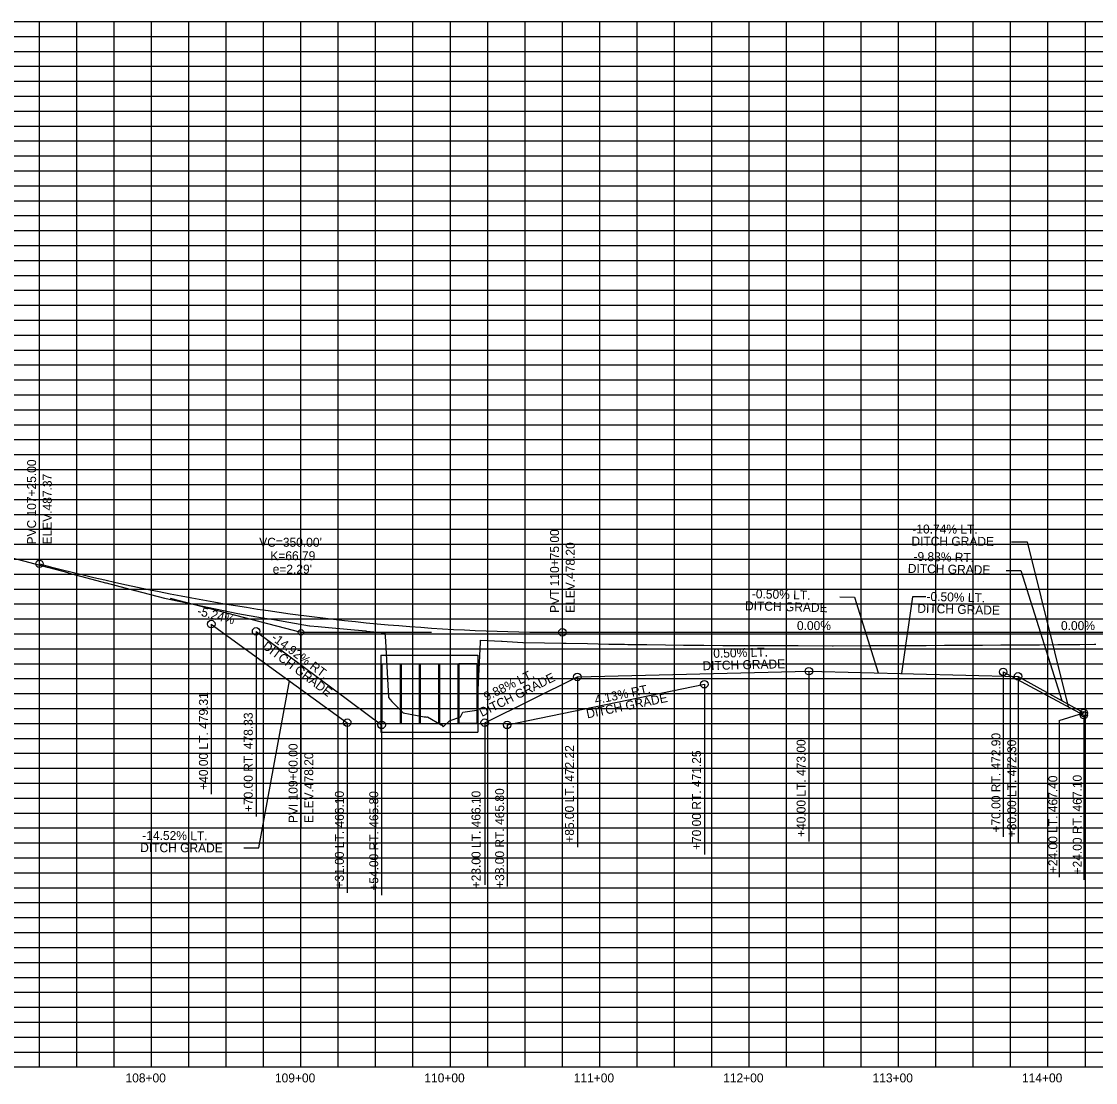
# Model space of a CAD drawing. Extents: x 1054002 to 1056762, y 395173 to 397393.
# Drawn here: x 1054745 to 1055464, y 396673 to 397383 of the extents above; entities that cross this region are included whole.
import ezdxf

# ---------------------------------------------------------------- set-up
doc = ezdxf.new("R2010")
doc.units = 0
for name, color, linetype in [('R_Axis_Annotation', 7, 'Continuous'), ('R_Drainage', 7, 'Continuous'), ('R_Exist Surface', 7, 'Continuous'), ('R_Grid', 7, 'Continuous'), ('R_Grid_Minor', 7, 'Continuous'), ('R_Vert Alg', 7, 'Continuous'), ('R_Vert Alg Annot', 7, 'Continuous')]:
    doc.layers.add(name, color=color, linetype=linetype)

msp = doc.modelspace()

# ---------------------------------------------------------------- linework, layer by layer
at = {"layer": 'R_Drainage'}
for p, q in [((1054985.8, 396959.15), (1054985.8, 396907.48)), ((1054985.8, 396959.15), (1055050.79, 396959.15)), ((1055050.79, 396959.15), (1055050.79, 396907.48)), ((1054986.48, 396953.31), (1054986.48, 396913.31)), ((1054986.48, 396953.31), (1054998.66, 396953.31)), ((1054998.66, 396953.31), (1054998.66, 396913.31)), ((1054999.34, 396953.31), (1054999.34, 396913.31)), ((1054999.34, 396953.31), (1055011.52, 396953.31)), ((1055011.52, 396953.31), (1055011.52, 396913.31)), ((1055012.2, 396953.31), (1055012.2, 396913.31)), ((1055012.2, 396953.31), (1055024.38, 396953.31)), ((1055024.38, 396953.31), (1055024.38, 396913.31)), ((1055025.06, 396953.31), (1055025.06, 396913.31)), ((1055025.06, 396953.31), (1055037.25, 396953.31)), ((1055037.25, 396953.31), (1055037.25, 396913.31)), ((1055037.92, 396953.31), (1055037.92, 396913.31)), ((1055050.11, 396953.31), (1055037.92, 396953.31)), ((1055050.11, 396953.31), (1055050.11, 396913.31)), ((1054986.48, 396913.31), (1054998.66, 396913.31)), ((1054999.34, 396913.31), (1055011.52, 396913.31)), ((1055012.2, 396913.31), (1055024.38, 396913.31)), ((1055025.06, 396913.31), (1055037.25, 396913.31)), ((1055050.11, 396913.31), (1055037.92, 396913.31)), ((1054985.8, 396907.48), (1055050.79, 396907.48))]:
    msp.add_line(p, q, dxfattribs=at)
at = {"layer": 'R_Exist Surface'}
msp.add_lwpolyline([(1054738.07, 397024.45), (1054750.91, 397021.1), (1054750.96, 397021.09), (1054762.42, 397018.05), (1054763.61, 397017.73), (1054776.24, 397014.37), (1054776.36, 397014.34), (1054788.99, 397010.97), (1054801.5, 397007.64), (1054801.84, 397007.55), (1054821.23, 397002.51), (1054821.42, 397002.45), (1054840.9, 396997.39), (1054840.92, 396997.38), (1054865.44, 396992.17), (1054865.46, 396992.17), (1054865.48, 396992.16), (1054890.01, 396986.95), (1054890.03, 396986.95), (1054890.06, 396986.94), (1054906.49, 396984.18), (1054914.1, 396982.89), (1054914.12, 396982.89), (1054938.12, 396978.85), (1054938.2, 396978.83), (1054943.83, 396978.31), (1054950.71, 396977.67), (1054950.83, 396977.65), (1054963.34, 396976.48), (1054975.63, 396975.32), (1054976.18, 396975.25), (1054988.47, 396974.09), (1054988.8, 396968.47), (1054991.01, 396930.7), (1054993.2, 396928.06), (1055000.64, 396920.56), (1055014.75, 396917.87), (1055015.95, 396917.83), (1055016.53, 396917.71), (1055016.93, 396917.93), (1055026.19, 396912.4), (1055026.58, 396912.41), (1055027.38, 396911.12), (1055031.82, 396915.26), (1055039.18, 396917.73), (1055040.63, 396920.89), (1055050.03, 396922.22), (1055050.17, 396922.27), (1055052.49, 396967.72), (1055052.55, 396969.21), (1055066.53, 396968.46), (1055066.9, 396968.44), (1055077.14, 396967.89), (1055080.92, 396967.67), (1055081.05, 396967.67), (1055095.37, 396967.39), (1055107.85, 396967.15), (1055109.76, 396967.12), (1055109.77, 396967.12), (1055124.16, 396966.84), (1055138.46, 396966.56), (1055138.62, 396966.56), (1055148.83, 396966.4), (1055151.12, 396966.37), (1055163.56, 396966.17), (1055163.77, 396966.16), (1055176.2, 396965.96), (1055188.44, 396965.76), (1055189, 396965.75), (1055201.86, 396965.71), (1055214.68, 396965.66), (1055215.3, 396965.67), (1055228.12, 396965.62), (1055228.77, 396965.63), (1055241.59, 396965.58), (1055264.46, 396965.5), (1055265.11, 396965.5), (1055288.02, 396965.43), (1055288.62, 396965.43), (1055313.1, 396965.53), (1055313.33, 396965.53), (1055327.32, 396965.59), (1055338, 396965.63), (1055338.1, 396965.63), (1055350.53, 396965.69), (1055350.67, 396965.69), (1055363.05, 396965.75), (1055363.25, 396965.75), (1055375.58, 396965.81), (1055375.82, 396965.8), (1055388.1, 396965.86), (1055388.4, 396965.86), (1055400.72, 396965.93), (1055401.36, 396965.94), (1055413.68, 396966.02), (1055425.92, 396966.09), (1055426.71, 396966.1), (1055438.95, 396966.18), (1055452.82, 396966.29), (1055453.62, 396966.3), (1055463.37, 396966.38), (1055464.37, 396966.39)], dxfattribs=at)
at = {"layer": 'R_Grid'}
for p, q in [((1054032.29, 397383.41), (1056732.29, 397383.41)), ((1054032.29, 397383.41), (1056732.29, 397383.41)), ((1054832.29, 396683.41), (1054832.29, 397383.41)), ((1054932.29, 396683.41), (1054932.29, 397383.41)), ((1055032.29, 396683.41), (1055032.29, 397383.41)), ((1055132.29, 396683.41), (1055132.29, 397383.41)), ((1055232.29, 396683.41), (1055232.29, 397383.41)), ((1055332.29, 396683.41), (1055332.29, 397383.41)), ((1055432.29, 396683.41), (1055432.29, 397383.41)), ((1054032.29, 397333.41), (1056732.29, 397333.41)), ((1054032.29, 397283.41), (1056732.29, 397283.41)), ((1054032.29, 397233.41), (1056732.29, 397233.41)), ((1054032.29, 397183.41), (1056732.29, 397183.41)), ((1054032.29, 397133.41), (1056732.29, 397133.41)), ((1054032.29, 397083.41), (1056732.29, 397083.41)), ((1054032.29, 397033.41), (1056732.29, 397033.41)), ((1054032.29, 396983.41), (1056732.29, 396983.41)), ((1054032.29, 396933.41), (1056732.29, 396933.41)), ((1054032.29, 396883.41), (1056732.29, 396883.41)), ((1054032.29, 396833.41), (1056732.29, 396833.41)), ((1054032.29, 396783.41), (1056732.29, 396783.41)), ((1054032.29, 396733.41), (1056732.29, 396733.41)), ((1054032.29, 396683.41), (1056732.29, 396683.41))]:
    msp.add_line(p, q, dxfattribs=at)
at = {"layer": 'R_Grid_Minor'}
for p, q in [((1054757.29, 396683.41), (1054757.29, 397383.41)), ((1054782.29, 396683.41), (1054782.29, 397383.41)), ((1054807.29, 396683.41), (1054807.29, 397383.41)), ((1054857.29, 396683.41), (1054857.29, 397383.41)), ((1054882.29, 396683.41), (1054882.29, 397383.41)), ((1054907.29, 396683.41), (1054907.29, 397383.41)), ((1054957.29, 396683.41), (1054957.29, 397383.41)), ((1054982.29, 396683.41), (1054982.29, 397383.41)), ((1055007.29, 396683.41), (1055007.29, 397383.41)), ((1055057.29, 396683.41), (1055057.29, 397383.41)), ((1055082.29, 396683.41), (1055082.29, 397383.41)), ((1055107.29, 396683.41), (1055107.29, 397383.41)), ((1055157.29, 396683.41), (1055157.29, 397383.41)), ((1055182.29, 396683.41), (1055182.29, 397383.41)), ((1055207.29, 396683.41), (1055207.29, 397383.41)), ((1055257.29, 396683.41), (1055257.29, 397383.41)), ((1055282.29, 396683.41), (1055282.29, 397383.41)), ((1055307.29, 396683.41), (1055307.29, 397383.41)), ((1055357.29, 396683.41), (1055357.29, 397383.41)), ((1055382.29, 396683.41), (1055382.29, 397383.41)), ((1055407.29, 396683.41), (1055407.29, 397383.41)), ((1055457.29, 396683.41), (1055457.29, 397383.41)), ((1054032.29, 397373.41), (1056732.29, 397373.41)), ((1054032.29, 397363.41), (1056732.29, 397363.41)), ((1054032.29, 397353.41), (1056732.29, 397353.41)), ((1054032.29, 397343.41), (1056732.29, 397343.41)), ((1054032.29, 397323.41), (1056732.29, 397323.41)), ((1054032.29, 397313.41), (1056732.29, 397313.41)), ((1054032.29, 397303.41), (1056732.29, 397303.41)), ((1054032.29, 397293.41), (1056732.29, 397293.41)), ((1054032.29, 397273.41), (1056732.29, 397273.41)), ((1054032.29, 397263.41), (1056732.29, 397263.41)), ((1054032.29, 397253.41), (1056732.29, 397253.41)), ((1054032.29, 397243.41), (1056732.29, 397243.41)), ((1054032.29, 397223.41), (1056732.29, 397223.41)), ((1054032.29, 397213.41), (1056732.29, 397213.41)), ((1054032.29, 397203.41), (1056732.29, 397203.41)), ((1054032.29, 397193.41), (1056732.29, 397193.41)), ((1054032.29, 397173.41), (1056732.29, 397173.41)), ((1054032.29, 397163.41), (1056732.29, 397163.41)), ((1054032.29, 397153.41), (1056732.29, 397153.41)), ((1054032.29, 397143.41), (1056732.29, 397143.41)), ((1054032.29, 397123.41), (1056732.29, 397123.41)), ((1054032.29, 397113.41), (1056732.29, 397113.41)), ((1054032.29, 397103.41), (1056732.29, 397103.41)), ((1054032.29, 397093.41), (1056732.29, 397093.41)), ((1054032.29, 397073.41), (1056732.29, 397073.41)), ((1054032.29, 397063.41), (1056732.29, 397063.41)), ((1054032.29, 397053.41), (1056732.29, 397053.41)), ((1054032.29, 397043.41), (1056732.29, 397043.41)), ((1054032.29, 397023.41), (1056732.29, 397023.41)), ((1054032.29, 397013.41), (1056732.29, 397013.41)), ((1054032.29, 397003.41), (1056732.29, 397003.41)), ((1054032.29, 396993.41), (1056732.29, 396993.41)), ((1054032.29, 396973.41), (1056732.29, 396973.41)), ((1054032.29, 396963.41), (1056732.29, 396963.41)), ((1054032.29, 396953.41), (1056732.29, 396953.41)), ((1054032.29, 396943.41), (1056732.29, 396943.41)), ((1054032.29, 396923.41), (1056732.29, 396923.41)), ((1054032.29, 396913.41), (1056732.29, 396913.41)), ((1054032.29, 396903.41), (1056732.29, 396903.41)), ((1054032.29, 396893.41), (1056732.29, 396893.41)), ((1054032.29, 396873.41), (1056732.29, 396873.41)), ((1054032.29, 396863.41), (1056732.29, 396863.41)), ((1054032.29, 396853.41), (1056732.29, 396853.41)), ((1054032.29, 396843.41), (1056732.29, 396843.41)), ((1054032.29, 396823.41), (1056732.29, 396823.41)), ((1054032.29, 396813.41), (1056732.29, 396813.41)), ((1054032.29, 396803.41), (1056732.29, 396803.41)), ((1054032.29, 396793.41), (1056732.29, 396793.41)), ((1054032.29, 396773.41), (1056732.29, 396773.41)), ((1054032.29, 396763.41), (1056732.29, 396763.41)), ((1054032.29, 396753.41), (1056732.29, 396753.41)), ((1054032.29, 396743.41), (1056732.29, 396743.41)), ((1054032.29, 396723.41), (1056732.29, 396723.41)), ((1054032.29, 396713.41), (1056732.29, 396713.41)), ((1054032.29, 396703.41), (1056732.29, 396703.41)), ((1054032.29, 396693.41), (1056732.29, 396693.41))]:
    msp.add_line(p, q, dxfattribs=at)
at = {"layer": 'R_Vert Alg'}
for p, q in [((1054872.29, 396979.96), (1054963.29, 396913.91)), ((1054902.29, 396975.06), (1054986.29, 396912.41)), ((1055107.29, 396974.41), (1055802.29, 396974.41)), ((1055117.29, 396944.54), (1055272.29, 396948.41)), ((1055272.29, 396948.41), (1055412.29, 396944.91)), ((1055402.29, 396947.91), (1055456.29, 396918.92)), ((1055412.29, 396944.91), (1055456.27, 396920.43)), ((1055055.29, 396913.91), (1055117.29, 396944.54)), ((1055070.29, 396912.41), (1055202.29, 396939.66))]:
    msp.add_line(p, q, dxfattribs=at)
msp.add_lwpolyline([(1054757.29, 397020.26), (1054764.58, 397018.37), (1054771.88, 397016.52), (1054779.17, 397014.71), (1054786.46, 397012.94), (1054793.75, 397011.21), (1054801.04, 397009.52), (1054808.33, 397007.87), (1054815.63, 397006.25), (1054822.92, 397004.68), (1054830.21, 397003.15), (1054837.5, 397001.66), (1054844.79, 397000.2), (1054852.08, 396998.79), (1054859.38, 396997.42), (1054866.67, 396996.08), (1054873.96, 396994.79), (1054881.25, 396993.54), (1054888.54, 396992.32), (1054895.83, 396991.15), (1054903.13, 396990.01), (1054910.42, 396988.92), (1054917.71, 396987.87), (1054925, 396986.85), (1054939.58, 396984.94), (1054946.88, 396984.04), (1054954.17, 396983.19), (1054961.46, 396982.37), (1054968.75, 396981.6), (1054976.04, 396980.86), (1054983.33, 396980.16), (1054990.63, 396979.51), (1054997.92, 396978.89), (1055005.21, 396978.31), (1055012.5, 396977.78), (1055019.79, 396977.28), (1055027.08, 396976.82), (1055034.38, 396976.4), (1055041.67, 396976.02), (1055048.96, 396975.69), (1055056.25, 396975.39), (1055063.54, 396975.13), (1055070.83, 396974.91), (1055078.13, 396974.73), (1055085.42, 396974.59), (1055092.71, 396974.49), (1055100, 396974.43), (1055107.29, 396974.41)], dxfattribs=at)
at = {"layer": 'R_Vert Alg Annot'}
for p, q in [((1054757.29, 397030.26), (1054757.29, 397114.26)), ((1055107.29, 396984.41), (1055107.29, 397068.41)), ((1054757.29, 397020.26), (1054757.29, 397030.26)), ((1054844.79, 396997.34), (1054932.29, 396974.41)), ((1055107.29, 396974.41), (1055107.29, 396984.41)), ((1054872.29, 396979.96), (1054872.29, 396949.96)), ((1054902.29, 396975.06), (1054902.29, 396935.06)), ((1054932.29, 396974.41), (1055019.79, 396974.41)), ((1054932.29, 396974.41), (1054932.29, 396927.7)), ((1054872.29, 396949.96), (1054872.29, 396865.96)), ((1055272.29, 396948.41), (1055272.29, 396918.41)), ((1055402.29, 396947.91), (1055402.29, 396921.53)), ((1055412.29, 396944.91), (1055412.29, 396917.52)), ((1055117.29, 396944.54), (1055117.29, 396914.54)), ((1055202.29, 396939.66), (1055202.29, 396909.66)), ((1054902.29, 396935.06), (1054902.29, 396851.06)), ((1054932.29, 396927.7), (1054932.29, 396843.7)), ((1055272.29, 396918.41), (1055272.29, 396834.41)), ((1055402.29, 396921.53), (1055402.29, 396837.53)), ((1055412.29, 396917.52), (1055412.29, 396833.52)), ((1055439.82, 396915.47), (1055456.27, 396920.43)), ((1055456.29, 396918.92), (1055456.29, 396808.73)), ((1054963.29, 396913.91), (1054963.29, 396883.91)), ((1054986.29, 396912.41), (1054986.29, 396882.41)), ((1055055.29, 396913.91), (1055055.29, 396882.53)), ((1055070.29, 396912.41), (1055070.29, 396881.46)), ((1055117.29, 396914.54), (1055117.29, 396830.54)), ((1055202.29, 396909.66), (1055202.29, 396825.66)), ((1055439.82, 396915.47), (1055439.82, 396810.4)), ((1054963.29, 396883.91), (1054963.29, 396799.91)), ((1054986.29, 396882.41), (1054986.29, 396798.41)), ((1055055.29, 396882.53), (1055055.29, 396805.29)), ((1055070.29, 396881.46), (1055070.29, 396804.22))]:
    msp.add_line(p, q, dxfattribs=at)
for points in [[(1055407.82, 397035.08), (1055418.46, 397035.05), (1055445.74, 396924.58)], [(1055404.38, 397015.78), (1055414.18, 397015.74), (1055441.46, 396928.66)], [(1055293.01, 396998.08), (1055302.82, 396998.04), (1055318.73, 396947.25)], [(1055350.57, 396998.13), (1055341.56, 396998.09), (1055334.22, 396946.86)], [(1054894.03, 396830.17), (1054904.21, 396830.23), (1054924.61, 396941.99)]]:
    msp.add_lwpolyline(points, dxfattribs=at)
for centre, radius in [((1054757.29, 397020.26), 2.5), ((1054872.29, 396979.96), 2.5), ((1054902.29, 396975.06), 2.5), ((1054932.29, 396974.41), 1.85), ((1055107.29, 396974.41), 2.5), ((1055117.29, 396944.54), 2.5), ((1055272.29, 396948.41), 2.5), ((1055402.29, 396947.91), 2.5), ((1055412.29, 396944.91), 2.5), ((1055202.29, 396939.66), 2.5), ((1054963.29, 396913.91), 2.5), ((1055055.29, 396913.91), 2.5), ((1055456.27, 396920.43), 2.5), ((1055456.29, 396918.92), 2.5), ((1054986.29, 396912.41), 2.5), ((1055070.29, 396912.41), 2.5)]:
    msp.add_circle(centre, radius, dxfattribs=at)

# ---------------------------------------------------------------- texts
at = {"layer": 'R_Axis_Annotation'}
for s, p in [('108+00', (1054814.89, 396673.06)), ('109+00', (1054914.89, 396673.06)), ('110+00', (1055014.89, 396673.06)), ('111+00', (1055114.89, 396673.06)), ('112+00', (1055214.89, 396673.06)), ('113+00', (1055314.89, 396673.06)), ('114+00', (1055414.89, 396673.06))]:
    msp.add_text(s, height=6, dxfattribs=at).set_placement(p)
at = {"layer": 'R_Vert Alg Annot'}
for s, rotation, p in [('PVC 107+25.00', 90, (1054755.04, 397033.26)), ('ELEV.487.37', 90, (1054765.54, 397033.26)), (' -10.74% LT.', 359.82298, (1055339.28, 397040.62)), ('PVT 110+75.00', 90, (1055105.04, 396987.41)), ('DITCH GRADE', 359.82298, (1055340.88, 397032.49)), ('ELEV.478.20', 90, (1055115.54, 396987.41)), (' -9.83% RT.', 358.8358, (1055339.98, 397022.35)), ('DITCH GRADE', 358.8358, (1055338.43, 397014.25)), ('-0.50% LT.', 358.5679, (1055234.03, 396997.27)), ('DITCH GRADE', 358.5679, (1055229.45, 396989.25)), ('-0.50% LT.', 358.5679, (1055350.92, 396995.49)), ('-5.24%', 345.06234, (1054862.49, 396986.18)), ('  DITCH GRADE', 358.5679, (1055340.34, 396987.62)), ('0.00%', 360, (1055264.28, 396975.91)), ('DITCH GRADE', 323.2832, (1054906.03, 396964.01)), ('-14.92% RT.', 323.2832, (1054911.99, 396969.7)), ('0.50% LT.', 1.4321, (1055208.34, 396957.33)), ('DITCH GRADE', 1.4321, (1055201.17, 396949.02)), ('DITCH GRADE', 26.28714, (1055053.39, 396917.7)), ('9.88% LT.', 26.28714, (1055056.41, 396928.26)), ('4.13% RT.', 11.66425, (1055129.55, 396926.18)), ('+40.00 LT. 479.31', 90, (1054870.04, 396868.96)), ('DITCH GRADE', 11.66425, (1055123.97, 396916.73)), ('+70.00 RT. 478.33', 90, (1054900.04, 396854.06)), ('+40.00 LT. 473.00', 90, (1055270.04, 396837.41)), ('+70.00 RT. 472.90', 90, (1055400.45, 396840.38)), ('+80.00 LT. 472.30', 90, (1055411.03, 396837.19)), ('PVI 109+00.00', 90, (1054930.04, 396846.7)), ('+85.00 LT. 472.22', 90, (1055115.04, 396833.54)), ('+70.00 RT. 471.25', 90, (1055200.04, 396828.66)), ('ELEV.478.20', 90, (1054940.54, 396846.7)), ('+24.00 LT. 467.40', 90, (1055438.57, 396813.18)), ('+24.00 RT. 467.10', 90, (1055454.89, 396812.31)), ('+31.00 LT. 466.10', 90, (1054961.04, 396802.91)), ('+54.00 RT. 465.80', 90, (1054984.04, 396801.41)), ('+23.00 LT. 466.10', 90, (1055052.48, 396802.99)), ('+38.00 RT. 465.80', 90, (1055068.3, 396803.29)), ('-14.52% LT.', 359.78437, (1054826.11, 396835.38)), ('DITCH GRADE', 359.78437, (1054824.7, 396827.26))]:
    msp.add_text(s, height=6, rotation=rotation, dxfattribs=at).set_placement(p)
for s, p in [("VC=350.00'", (1054904.39, 397031.71)), ('K=66.79', (1054911.82, 397022.71)), ("e=2.29'", (1054913.39, 397013.71)), ('0.00%', (1055440.99, 396975.91))]:
    msp.add_text(s, height=6, dxfattribs=at).set_placement(p)

doc.saveas('drawing.dxf')
